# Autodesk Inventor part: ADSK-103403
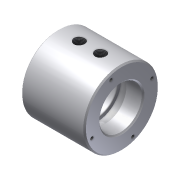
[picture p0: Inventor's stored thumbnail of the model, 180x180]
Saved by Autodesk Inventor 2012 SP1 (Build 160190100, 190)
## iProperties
Shininess: 21.0
Created: 2001-04
Part Number: ADSK-103403
Document SubType Name: Modeling
Designer: Administrator
Stock Number: ADSK-103403
Density: 1 g/cm^3
Material: Default
Density: 0.0
Volumn: 0.0
Area: 0.0
PropertySet Name: Model Information
Control State: 0
Master: False
Checked Out: False
Author: Administrator
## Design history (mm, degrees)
sketch "Sketch1"
  geometry: L1 (-34.557, 0.958)-(41.389, 0.958); L2 (41.389, 0.958)-(41.389, 45.408); L3 (41.389, 45.408)-(-34.557, 45.408); L4 (-34.557, 45.408)-(-34.557, 0.958); L5 (-34.557, 26.358)-(-13.983, 26.358); L6 (-13.983, 26.358)-(-13.983, 30.422); L7 (-13.983, 30.422)-(-4.458, 30.422); L8 (-4.458, 30.422)-(-4.458, 26.358); L9 (-4.458, 26.358)-(11.29, 26.358); L10 (11.29, 26.358)-(11.29, 30.422); L11 (11.29, 30.422)-(20.815, 30.422); L12 (20.815, 30.422)-(20.815, 26.358); L13 (20.815, 26.358)-(41.389, 26.358)
  constraints: 26 end point, 4 parallel, 2 collinear, 2 perpendicular, 2 point on line, 1 horizontal
  dimensions: "d3" = 44.45 distance between parallel lines of L1 L3; "d4" = 25.4 distance between parallel lines of L1 L5; "d5" = 25.4 distance between parallel lines of L1 L13 (= d4); "d19" = 9.525 distance of L10.end L11.end; "d26" = 9.525 distance of L6.end L7.end; "d32" = 29.464 distance between parallel lines of L1 L7 (= d30); "d34" = 29.464 distance between parallel lines of L1 L11 (= d30); "d37" = 75.946 distance of L2.end L3.end (derived)
revolve "Revolution1" sketch "Sketch1" stored, may be unused: angle "d0" = 90 deg
chamfer "Chamfer1" distance "d1" = 1.5875; stored, may be unused: second distance "d2" = 1.5875, angle "d75" = 45 deg
workaxis "Work Axis1"
workplane "Work Plane1"
sketch "Sketch2"
  geometry: L1 (53.162, 0)-(-53.162, 0) reference; L2 (-17.399, 29.464)-(-17.399, -29.464) reference; L3 (-7.874, 25.4)-(-7.874, -25.4) reference; L4 (7.874, 29.464)-(7.874, -29.464) reference; L5 (17.399, 25.4)-(17.399, -25.4) reference; L6 (7.874, 29.464)-(17.399, 29.464) reference; L7 (7.874, -29.464)-(17.399, -29.464) reference; L8 (-17.399, 29.464)-(-7.874, 29.464) reference; L9 (-17.399, -29.464)-(-7.874, -29.464) reference; L10 (-12.637, 29.464)-(-12.637, -29.464); L11 (12.636, 29.464)-(12.636, -29.464); 2 further points
  constraints: 6 midpoint, 4 end point
hole "Hole1" sketch "Sketch2" at (-12.637, 0), (12.636, 0) diameter "d38" = 7.9375; stored, may be unused: countersink angle "d42" = 60 deg, drill point angle "d44" = 118 deg; dims "d39" = 12.7, "d40" = 12.7, "d41" = 12.7, "d43" = 25.4
thread "Thread3" dims "d49" = 25.4, "d50" = 0
thread "Thread4" dims "d51" = 25.4, "d52" = 0
sketch "Sketch4"
  geometry: L1 (0, 0)-(0, 38.1); L2 (0, 0)-(-13.031, 35.802); C1 r 42.863 at (0, 0) reference; C2 r 26.988 at (0, 0) reference; A1 r 38.1 centre (0, 0) between (0, 38.1) and (-13.031, 35.802); 1 further point
  constraints: 4 end point, 2 point on circle, 1 centre point, 1 coincident, 1 vertical
  dimensions: "d62" = 20 deg angle of L1 L2; "d70" = 76.2 diameter of A1
hole "Hole3" sketch "Sketch4" at (-13.031, 35.802) diameter "d63" = 3.683; stored, may be unused: countersink angle "d67" = 60 deg, drill point angle "d69" = 118 deg; dims "d64" = 12.7, "d65" = 9.525, "d66" = 6.35, "d68" = 19.05
fillet "Fillet1" dims "d71" = 1.27
pattern_circular "Circular Pattern1" dims angle "d74" = 360 deg
body "Solid1"
other parameters: "d30" = 29.464
